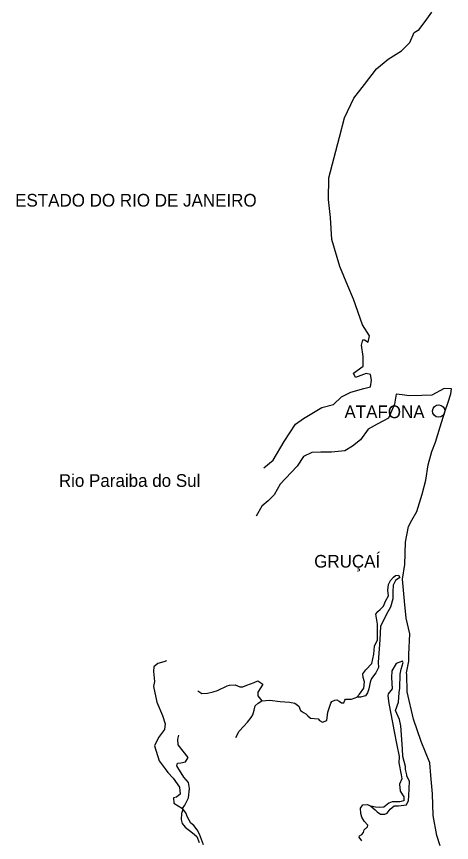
# Model space of a CAD drawing. Extents: x 662444 to 1640468, y 7452018 to 9606170.
# Drawn here: x 891529 to 913344, y 7581610 to 7623052 of the extents above; entities that cross this region are included whole.
import ezdxf

# ---------------------------------------------------------------- set-up
doc = ezdxf.new("R2010")
doc.units = 0
for name, color, linetype in [('Level 1', 7, 'Continuous'), ('Level 2', 7, 'Continuous'), ('Level 3', 7, 'Continuous')]:
    doc.layers.add(name, color=color, linetype=linetype)

msp = doc.modelspace()

# ---------------------------------------------------------------- linework, layer by layer
at = {"layer": 'Level 1'}
for points in [[(903938, 7600405), (904404, 7600793), (904957, 7601733), (905529, 7602606), (905930, 7602884), (906836, 7603427), (907421, 7603590), (907824, 7603968), (908297, 7604200), (908945, 7604383), (909279, 7604475), (909329, 7604806), (909285, 7605085), (909058, 7605135), (908523, 7604938), (908425, 7605151), (908911, 7605505), (908913, 7605993), (908824, 7606561), (908893, 7606825), (908976, 7606823), (909160, 7606708), (909231, 7607039), (908881, 7607580), (908436, 7608867), (908152, 7609540), (907741, 7610505), (907339, 7611857), (907284, 7612968), (907172, 7613870), (907199, 7614956), (907729, 7617006), (907971, 7617966), (908442, 7618952), (908989, 7619637), (909580, 7620421), (910164, 7620906), (910839, 7621332), (911255, 7621755), (911465, 7622248), (911728, 7622397), (912105, 7622920), (912353, 7623269)], [(911353, 7597787), (911612, 7598215), (911880, 7599094), (912054, 7599788), (912177, 7600551), (912361, 7601234), (912538, 7601695), (912776, 7602466), (913013, 7603214), (913182, 7603709), (913317, 7604116), (913344, 7604371), (912971, 7604380), (912360, 7604052), (911862, 7604031), (911218, 7604015), (910877, 7604068), (910577, 7604098), (910492, 7603601), (910183, 7602898), (909616, 7602602), (909173, 7602347), (908776, 7601814), (908384, 7601502), (907995, 7601268), (907329, 7601196), (906790, 7601198), (906333, 7601177), (905923, 7600976), (905599, 7600485), (905024, 7599878), (904757, 7599586), (904443, 7599050), (904147, 7598757), (903830, 7598476), (903548, 7597985)], [(912311, 7584964), (912259, 7585603), (911820, 7586680), (911445, 7587799), (911117, 7589161), (911098, 7590038), (911080, 7590127), (911198, 7590701), (911207, 7591045), (911254, 7592075), (911067, 7592857), (910996, 7593724), (910889, 7594814), (911012, 7595554), (911030, 7596675), (911185, 7597469), (911353, 7597787)], [(908592, 7588904), (908730, 7589056), (908956, 7589361), (908974, 7589671), (908918, 7589894), (908891, 7590072), (909052, 7590268), (909350, 7590582), (909445, 7591057), (909476, 7591466), (909629, 7591784), (909639, 7592161), (909639, 7592561), (909548, 7593073), (909645, 7593204), (909762, 7593301), (909932, 7593474), (910042, 7593726), (910183, 7593978), (910150, 7594278), (910188, 7594555), (910286, 7594763), (910436, 7594926), (910531, 7595001), (910687, 7595019), (910757, 7594906), (910535, 7594757), (910425, 7594526), (910407, 7594194), (910408, 7593828), (910283, 7593410), (910087, 7593071), (909978, 7592852), (909781, 7592457), (909753, 7591770), (909663, 7590652), (909677, 7590385), (909545, 7590122), (909331, 7589839), (909274, 7589652), (909204, 7589321), (909136, 7589123), (909029, 7588970), (908788, 7588899), (908592, 7588904)], [(899050, 7590721), (898914, 7590680), (898612, 7590587), (898421, 7590415), (898405, 7590182), (898444, 7589693), (898407, 7589439), (898574, 7588647), (898858, 7587985), (898992, 7587560), (898943, 7587273), (898643, 7586870), (898457, 7586453), (898676, 7585704), (898983, 7585304)], [(911100, 7584996), (911037, 7585268), (911041, 7585424), (910909, 7585926), (910888, 7586315), (910804, 7587471), (910729, 7587784), (910533, 7588233), (910679, 7588651), (910722, 7589127), (910749, 7589348), (910767, 7590057), (910825, 7590311), (910917, 7590642), (910887, 7590709), (910563, 7590584), (910357, 7590223), (910338, 7589891), (910364, 7589313), (910161, 7589063), (910158, 7588964), (910200, 7588585), (910393, 7587626), (910446, 7587270), (910603, 7586489), (910713, 7585931), (910704, 7585610), (910820, 7585003)], [(900619, 7589217), (900823, 7589090), (901113, 7589094), (901385, 7589175), (901614, 7589236), (902097, 7589468), (902212, 7589510), (902492, 7589514), (902728, 7589419), (902883, 7589415), (903082, 7589499), (903449, 7589645), (903627, 7589718), (903882, 7589545), (903774, 7589381), (903633, 7589152), (903629, 7588964), (903840, 7588714)], [(902529, 7586883), (902703, 7587190), (902927, 7587439), (903119, 7587645), (903290, 7587874), (903387, 7588016), (903455, 7588247), (903502, 7588468), (903650, 7588597), (903840, 7588714), (904235, 7588749), (904751, 7588691), (905217, 7588646), (905495, 7588595), (905688, 7588445), (905776, 7588232), (905919, 7588140), (906031, 7588071), (906143, 7587968), (906274, 7587842), (906657, 7587822), (906727, 7587731), (906870, 7587650), (907090, 7587722), (907142, 7588153), (907288, 7588593), (907342, 7588681), (907489, 7588755), (907593, 7588763), (907716, 7588704), (907828, 7588624), (907942, 7588621), (907987, 7588753), (908030, 7588807), (908257, 7588802), (908330, 7588800), (908518, 7588861), (908592, 7588904)], [(899669, 7585286), (899561, 7585460), (899595, 7585582), (899772, 7585599), (900012, 7585660), (900141, 7585878), (899890, 7586195), (899629, 7586513), (899626, 7586801), (899672, 7586989)], [(898983, 7585304), (899118, 7585128), (899390, 7584843), (899700, 7584381), (899743, 7584036), (899553, 7583885), (899407, 7583856), (899421, 7583589), (899860, 7583323)], [(899860, 7583323), (899978, 7583486), (900153, 7583848), (900206, 7584324), (900151, 7584625), (899920, 7584886), (899701, 7585235), (899669, 7585286)], [(910820, 7585003), (910859, 7584796), (910739, 7584533), (910771, 7584188), (910950, 7583906), (910955, 7583695), (910758, 7583656), (910364, 7583655), (910196, 7583581), (909952, 7583377), (909724, 7583372), (909528, 7583377), (909291, 7583438)], [(911200, 7583955), (911240, 7584686), (911112, 7584945), (911100, 7584996)], [(912772, 7581440), (912610, 7581955), (912428, 7582958), (912384, 7584058), (912311, 7584964)], [(909291, 7583438), (909514, 7583244), (909615, 7583141), (909778, 7583026), (910006, 7583032), (910121, 7583073), (910271, 7583280), (910462, 7583453), (910680, 7583447), (911085, 7583503), (911184, 7583722), (911200, 7583955)], [(908852, 7581685), (908722, 7581877), (908724, 7581944), (908850, 7582018), (908935, 7582105), (908970, 7582237), (909130, 7582400), (909142, 7582477), (908961, 7582681), (908842, 7582884), (908805, 7583062), (908781, 7583340), (908899, 7583504), (909127, 7583520), (909291, 7583438)], [(900912, 7581499), (900708, 7582026), (900589, 7582251), (900418, 7582466), (900266, 7582580), (900097, 7582884), (900020, 7583097), (899860, 7583323), (899857, 7583223), (899801, 7583058), (899794, 7582759), (899830, 7582569), (899991, 7582377), (900357, 7582101), (900580, 7581907), (900697, 7581604)]]:
    msp.add_lwpolyline(points, dxfattribs=at)
at = {"layer": 'Level 2'}
msp.add_ellipse((912703, 7603255), major_axis=(311, -12), ratio=0.999998, dxfattribs=at)

# ---------------------------------------------------------------- texts
at = {"layer": 'Level 3'}
for s, height, p in [('ESTADO DO RIO DE JANEIRO', 636.86, (891459, 7613515)), ('ATAFONA', 636.5, (907976, 7602900)), ('Rio Paraiba do Sul', 636.32, (893653, 7599453)), ('GRUÇAÍ', 636.2, (906459, 7595402))]:
    msp.add_text(s, height=height, dxfattribs=at).set_placement(p)

doc.saveas('drawing.dxf')
